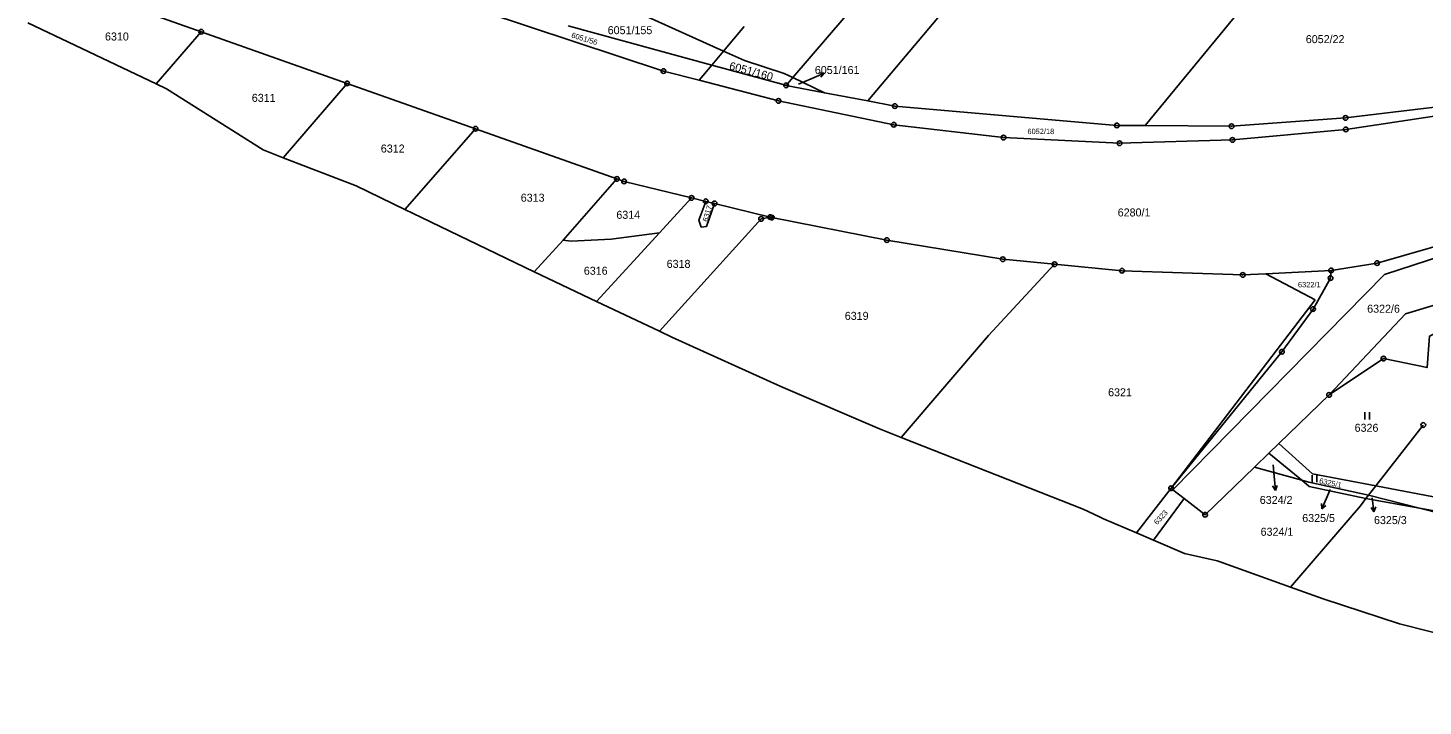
# Model space of a CAD drawing. Extents: x -644096 to -634268, y -1141430 to -1133463.
# Drawn here: x -639603.2 to -639306.8, y -1139602.6 to -1139458.6 of the extents above; entities that cross this region are included whole.
import ezdxf

# ---------------------------------------------------------------- set-up
doc = ezdxf.new("R2010")
doc.units = 0
for name, color, linetype in [('_CIVIL_CONSTRUCTION', 7, 'Continuous'), ('svrsek_osa_sjezdy', 7, 'Continuous'), ('svrsek_osa_VRT', 7, 'Continuous'), ('svrsek_popisy_VRT', 7, 'Continuous'), ('terminal_VRT', 7, 'Continuous')]:
    doc.layers.add(name, color=color, linetype=linetype)

msp = doc.modelspace()

# ---------------------------------------------------------------- linework, layer by layer
at = {"layer": '_CIVIL_CONSTRUCTION'}
for centre, radius in [((-639566.35, -1139459.39), 0.5), ((-639566.35, -1139459.39), 0.0303), ((-639468.16, -1139467.73), 0.5), ((-639468.16, -1139467.73), 0.0303), ((-639535.38, -1139470.35), 0.5), ((-639535.38, -1139470.35), 0.0303), ((-639442.11, -1139470.76), 0.5), ((-639442.11, -1139470.76), 0.0303), ((-639443.72, -1139474.07), 0.5), ((-639443.72, -1139474.07), 0.0303), ((-639419, -1139475.17), 0.5), ((-639419, -1139475.17), 0.0303), ((-639323.25, -1139477.69), 0.5), ((-639323.25, -1139477.69), 0.0303), ((-639508.09, -1139479.99), 0.5), ((-639508.09, -1139479.99), 0.0303), ((-639419.25, -1139479.12), 0.5), ((-639419.25, -1139479.12), 0.0303), ((-639371.83, -1139479.28), 0.5), ((-639371.83, -1139479.28), 0.0303), ((-639347.47, -1139479.44), 0.5), ((-639347.47, -1139479.44), 0.0303), ((-639323.2, -1139480.13), 0.5), ((-639323.2, -1139480.13), 0.0303), ((-639395.91, -1139481.86), 0.5), ((-639395.91, -1139481.86), 0.0303), ((-639371.25, -1139483.05), 0.5), ((-639371.25, -1139483.05), 0.0303), ((-639347.29, -1139482.36), 0.5), ((-639347.29, -1139482.36), 0.0303), ((-639478.04, -1139490.62), 0.5), ((-639478.04, -1139490.62), 0.0303), ((-639476.51, -1139491.16), 0.5), ((-639476.51, -1139491.16), 0.0303), ((-639462.17, -1139494.66), 0.5), ((-639462.17, -1139494.66), 0.0303), ((-639459.19, -1139495.39), 0.5), ((-639459.19, -1139495.39), 0.0303), ((-639457.3, -1139495.85), 0.5), ((-639457.3, -1139495.85), 0.0303), ((-639447.41, -1139499.13), 0.5), ((-639447.41, -1139499.13), 0.0303), ((-639445.52, -1139498.73), 0.5), ((-639445.13, -1139498.83), 0.5), ((-639445.52, -1139498.73), 0.0303), ((-639445.13, -1139498.83), 0.0303), ((-639420.69, -1139503.63), 0.5), ((-639420.69, -1139503.63), 0.0303), ((-639396.06, -1139507.69), 0.5), ((-639396.06, -1139507.69), 0.0303), ((-639316.54, -1139508.49), 0.5), ((-639385.08, -1139508.75), 0.5), ((-639385.08, -1139508.75), 0.0303), ((-639370.74, -1139510.14), 0.5), ((-639370.74, -1139510.14), 0.0303), ((-639345.1, -1139511.02), 0.5), ((-639326.32, -1139510.07), 0.5), ((-639326.32, -1139510.07), 0.0303), ((-639316.54, -1139508.49), 0.0303), ((-639345.1, -1139511.02), 0.0303), ((-639326.43, -1139511.69), 0.5), ((-639326.43, -1139511.69), 0.0303), ((-639330.16, -1139518.28), 0.5), ((-639330.16, -1139518.28), 0.0303), ((-639336.76, -1139527.33), 0.5), ((-639336.76, -1139527.33), 0.0303), ((-639315.19, -1139528.78), 0.5), ((-639315.19, -1139528.78), 0.0303), ((-639326.74, -1139536.48), 0.5), ((-639326.74, -1139536.48), 0.0303), ((-639306.72, -1139542.88), 0.5), ((-639360.32, -1139556.3), 0.5), ((-639360.32, -1139556.3), 0.0303), ((-639353.1, -1139561.94), 0.5), ((-639353.1, -1139561.94), 0.0303)]:
    msp.add_circle(centre, radius, dxfattribs=at)
at = {"layer": 'svrsek_osa_sjezdy'}
for p, q in [((-639319.14, -1139541.68), (-639319.14, -1139540.18)), ((-639318.14, -1139541.68), (-639318.14, -1139540.18)), ((-639330.32, -1139555.02), (-639330.32, -1139553.52)), ((-639329.32, -1139555.02), (-639329.32, -1139553.52))]:
    msp.add_line(p, q, dxfattribs=at)
at = {"layer": 'svrsek_popisy_VRT'}
for p, q in [((-639439.49, -1139470.49), (-639436.79, -1139469.37)), ((-639436.79, -1139469.37), (-639434.03, -1139468.2)), ((-639434.03, -1139468.2), (-639435.15, -1139468.13)), ((-639434.03, -1139468.2), (-639434.75, -1139469.05)), ((-639338.64, -1139551.36), (-639338.42, -1139553.77)), ((-639338.42, -1139553.77), (-639338.16, -1139556.76)), ((-639338.16, -1139556.76), (-639338.74, -1139555.81)), ((-639338.16, -1139556.76), (-639337.75, -1139555.72)), ((-639327.09, -1139557.92), (-639328.31, -1139560.66)), ((-639326.48, -1139556.54), (-639327.09, -1139557.92)), ((-639317.58, -1139558.37), (-639317.21, -1139561.35)), ((-639328.31, -1139560.66), (-639328.36, -1139559.54)), ((-639328.31, -1139560.66), (-639327.45, -1139559.95)), ((-639317.21, -1139561.35), (-639317.83, -1139560.42)), ((-639317.21, -1139561.35), (-639316.84, -1139560.29))]:
    msp.add_line(p, q, dxfattribs=at)
at = {"layer": 'terminal_VRT'}
for p, q in [((-639412.84, -1139436.75), (-639440.68, -1139469.09)), ((-639538.11, -1139444.58), (-639468.16, -1139467.73)), ((-639595.97, -1139448.92), (-639566.35, -1139459.39)), ((-639575.92, -1139470.45), (-639603.19, -1139457.48)), ((-639575.92, -1139470.45), (-639566.35, -1139459.39)), ((-639566.35, -1139459.39), (-639535.38, -1139470.35)), ((-639457.89, -1139466.45), (-639488.42, -1139458.13)), ((-639455.39, -1139463.48), (-639450.99, -1139458.25)), ((-639457.89, -1139466.45), (-639455.39, -1139463.48)), ((-639450.94, -1139465.52), (-639455.39, -1139463.48)), ((-639460.59, -1139469.69), (-639457.89, -1139466.45)), ((-639442.5, -1139468.22), (-639450.94, -1139465.52)), ((-639468.16, -1139467.73), (-639460.59, -1139469.69)), ((-639440.68, -1139469.09), (-639442.5, -1139468.22)), ((-639442.11, -1139470.76), (-639440.68, -1139469.09)), ((-639440.68, -1139469.09), (-639433.95, -1139472.32)), ((-639548.97, -1139486.13), (-639535.38, -1139470.35)), ((-639535.38, -1139470.35), (-639508.09, -1139479.99)), ((-639460.59, -1139469.69), (-639443.72, -1139474.07)), ((-639433.95, -1139472.32), (-639442.11, -1139470.76)), ((-639424.76, -1139474.07), (-639433.95, -1139472.32)), ((-639419, -1139475.17), (-639424.76, -1139474.07)), ((-639371.83, -1139479.28), (-639419, -1139475.17)), ((-639523.08, -1139497.13), (-639508.09, -1139479.99)), ((-639508.09, -1139479.99), (-639478.04, -1139490.62)), ((-639365.84, -1139479.32), (-639371.83, -1139479.28)), ((-639347.47, -1139479.44), (-639365.84, -1139479.32)), ((-639489.46, -1139503.61), (-639478.04, -1139490.62)), ((-639469, -1139502.05), (-639462.17, -1139494.66)), ((-639459.19, -1139495.39), (-639462.17, -1139494.66)), ((-639459.19, -1139495.39), (-639457.3, -1139495.85)), ((-639445.52, -1139498.73), (-639457.3, -1139495.85)), ((-639523.08, -1139497.13), (-639519.58, -1139498.82)), ((-639519.58, -1139498.82), (-639495.62, -1139510.38)), ((-639447.41, -1139499.13), (-639445.52, -1139498.73)), ((-639445.52, -1139498.73), (-639445.13, -1139498.83)), ((-639482.39, -1139516.64), (-639469, -1139502.05)), ((-639469.03, -1139522.96), (-639447.41, -1139499.13)), ((-639495.62, -1139510.38), (-639489.46, -1139503.61)), ((-639482.39, -1139516.64), (-639495.62, -1139510.38)), ((-639345.1, -1139511.02), (-639340.17, -1139510.77)), ((-639340.17, -1139510.77), (-639326.32, -1139510.07)), ((-639329.71, -1139516.33), (-639340.17, -1139510.77)), ((-639469.03, -1139522.96), (-639482.39, -1139516.64)), ((-639360.32, -1139556.3), (-639329.71, -1139516.33)), ((-639326.74, -1139536.48), (-639337.41, -1139546.79)), ((-639316.79, -1139555.79), (-639306.72, -1139542.88)), ((-639342.6, -1139551.81), (-639339.51, -1139548.83)), ((-639337.41, -1139546.79), (-639339.51, -1139548.83)), ((-639339.51, -1139548.83), (-639332.55, -1139554.62)), ((-639332.55, -1139554.62), (-639342.6, -1139551.81)), ((-639367.64, -1139565.8), (-639360.32, -1139556.3)), ((-639360.32, -1139556.3), (-639359.91, -1139556.62)), ((-639357.52, -1139558.49), (-639359.91, -1139556.62)), ((-639318.37, -1139557.81), (-639318.91, -1139558.5)), ((-639318.37, -1139557.81), (-639316.79, -1139555.79)), ((-639318.37, -1139557.81), (-639307.5, -1139560.55)), ((-639249.55, -1139568.77), (-639316.79, -1139555.79)), ((-639364.07, -1139567.34), (-639357.52, -1139558.49)), ((-639320.1, -1139560.02), (-639334.97, -1139577.29)), ((-639318.91, -1139558.5), (-639320.1, -1139560.02)), ((-639318.91, -1139558.5), (-639307.5, -1139560.55)), ((-639375.53, -1139562.37), (-639374.65, -1139562.78)), ((-639374.65, -1139562.78), (-639367.64, -1139565.8)), ((-639367.64, -1139565.8), (-639364.07, -1139567.34)), ((-639357.46, -1139570.18), (-639364.07, -1139567.34)), ((-639334.97, -1139577.29), (-639350.11, -1139571.88))]:
    msp.add_line(p, q, dxfattribs=at)
for points in [[(-639383.43, -1139424.7), (-639384.33, -1139426.05), (-639424.76, -1139474.07)], [(-639365.84, -1139479.32), (-639337.25, -1139444.6), (-639334.55, -1139440.92)], [(-639455.39, -1139463.48), (-639473.6, -1139455.3), (-639481.44, -1139450.3)], [(-639442.11, -1139470.76), (-639442.71, -1139470.59), (-639457.89, -1139466.45)], [(-639292.46, -1139464.12), (-639300.17, -1139474.9), (-639323.25, -1139477.69), (-639347.47, -1139479.44)], [(-639575.92, -1139470.45), (-639573.77, -1139471.47), (-639553.21, -1139484.49), (-639548.97, -1139486.13)], [(-639443.72, -1139474.07), (-639419.25, -1139479.12), (-639395.91, -1139481.86), (-639371.25, -1139483.05), (-639347.29, -1139482.36), (-639323.2, -1139480.13), (-639299.69, -1139476.63)], [(-639548.97, -1139486.13), (-639533.48, -1139492.12), (-639523.08, -1139497.13)], [(-639478.04, -1139490.62), (-639476.51, -1139491.16), (-639462.17, -1139494.66)], [(-639457.3, -1139495.85), (-639459.05, -1139500.7), (-639460.13, -1139500.85), (-639460.62, -1139499.36), (-639459.19, -1139495.39)], [(-639445.13, -1139498.83), (-639420.69, -1139503.63), (-639396.06, -1139507.69), (-639385.08, -1139508.75)], [(-639489.46, -1139503.61), (-639487.76, -1139503.87), (-639479.25, -1139503.44), (-639469, -1139502.05)], [(-639326.32, -1139510.07), (-639316.54, -1139508.49), (-639294.37, -1139502.18)], [(-639359.91, -1139556.62), (-639314.97, -1139510.89), (-639299.52, -1139505.93)], [(-639417.63, -1139545.51), (-639399.12, -1139523.9), (-639385.08, -1139508.75)], [(-639385.08, -1139508.75), (-639370.74, -1139510.14), (-639345.1, -1139511.02)], [(-639360.32, -1139556.3), (-639336.76, -1139527.33), (-639330.16, -1139518.28), (-639326.43, -1139511.69), (-639326.32, -1139510.07)], [(-639326.74, -1139536.48), (-639310.49, -1139519.3), (-639298.01, -1139515.53)], [(-639469.03, -1139522.96), (-639466.36, -1139524.23), (-639443.22, -1139534.68), (-639422.25, -1139543.69), (-639417.63, -1139545.51)], [(-639294.22, -1139524.05), (-639303.47, -1139523), (-639305.43, -1139524.04), (-639305.93, -1139530.68), (-639315.19, -1139528.78), (-639326.74, -1139536.48)], [(-639375.53, -1139562.37), (-639379, -1139560.74), (-639417.63, -1139545.51)], [(-639316.79, -1139555.79), (-639330.29, -1139553.24), (-639337.41, -1139546.79)], [(-639357.52, -1139558.49), (-639353.1, -1139561.94), (-639342.6, -1139551.81)], [(-639318.91, -1139558.5), (-639330.94, -1139555.96), (-639332.55, -1139554.62)], [(-639332.55, -1139554.62), (-639331.07, -1139555.04), (-639318.37, -1139557.81)], [(-639307.5, -1139560.55), (-639250.16, -1139570.87), (-639237.56, -1139580.03)], [(-639307.5, -1139560.55), (-639288.29, -1139565.4), (-639246.7, -1139578.23), (-639237.56, -1139580.03)], [(-639357.46, -1139570.18), (-639350.53, -1139571.73), (-639350.11, -1139571.88)], [(-639238.95, -1139602.56), (-639243.1, -1139601.54), (-639286.59, -1139591.44), (-639311.79, -1139585.12), (-639328.01, -1139579.78), (-639334.97, -1139577.29)]]:
    msp.add_lwpolyline(points, dxfattribs=at)

# ---------------------------------------------------------------- texts
at = {"layer": 'svrsek_osa_VRT'}
for s, height, p in [('6310', 1.7, (-639586.81, -1139461.24)), ('6051/155', 1.7, (-639480.01, -1139459.9)), ('6052/22', 1.7, (-639331.69, -1139461.8)), ('6051/161', 1.7, (-639436, -1139468.35)), ('6311', 1.7, (-639555.62, -1139474.27)), ('6052/18', 1.14, (-639390.83, -1139481.11)), ('6312', 1.7, (-639528.21, -1139485.03)), ('6313', 1.7, (-639498.48, -1139495.47)), ('6314', 1.7, (-639478.17, -1139499.1)), ('6280/1', 1.7, (-639371.65, -1139498.6)), ('6318', 1.7, (-639467.48, -1139509.52)), ('6316', 1.7, (-639485.08, -1139510.98)), ('6322/1', 1.14, (-639333.35, -1139513.65)), ('6319', 1.7, (-639429.64, -1139520.56)), ('6322/6', 1.7, (-639318.65, -1139519.04)), ('6321', 1.7, (-639373.69, -1139536.78)), ('6326', 1.7, (-639321.32, -1139544.32)), ('6324/2', 1.7, (-639341.47, -1139559.64)), ('6325/5', 1.7, (-639332.45, -1139563.48)), ('6325/3', 1.7, (-639317.2, -1139563.92)), ('6324/1', 1.7, (-639341.29, -1139566.4))]:
    msp.add_text(s, height=height, dxfattribs=at).set_placement(p)
for s, height, rotation, p in [('6051/56', 1.14, 343, (-639487.83, -1139460.58)), ('6051/160', 1.7, 345, (-639454.31, -1139467.37)), ('6317', 1.14, 73, (-639458.82, -1139499.82)), ('6325/1', 1.139, 348, (-639328.92, -1139555.24)), ('6323', 1.14, 47, (-639363.29, -1139564.16))]:
    msp.add_text(s, height=height, rotation=rotation, dxfattribs=at).set_placement(p)

doc.saveas('drawing.dxf')
